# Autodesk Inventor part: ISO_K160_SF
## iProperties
Created: 2005-11
Part Number: ISO_K160_SF
Material: 1.4301 X5CrNi10-10 A2
Description: Flansch DN160 ISO-K
Document SubType Name: Modellieren
Designer: Mittelmeyer
Manufacturer: Standard
Standards Organization: Custom
Author: Mittelmeyer
Comments: LEYBOLD
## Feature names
1. Extrusion2
2. Extrusion3
3. Extrusion4
4. Drehung1 [Revolution]
5. Bohrung1 [Hole]
6. Extrusion5
